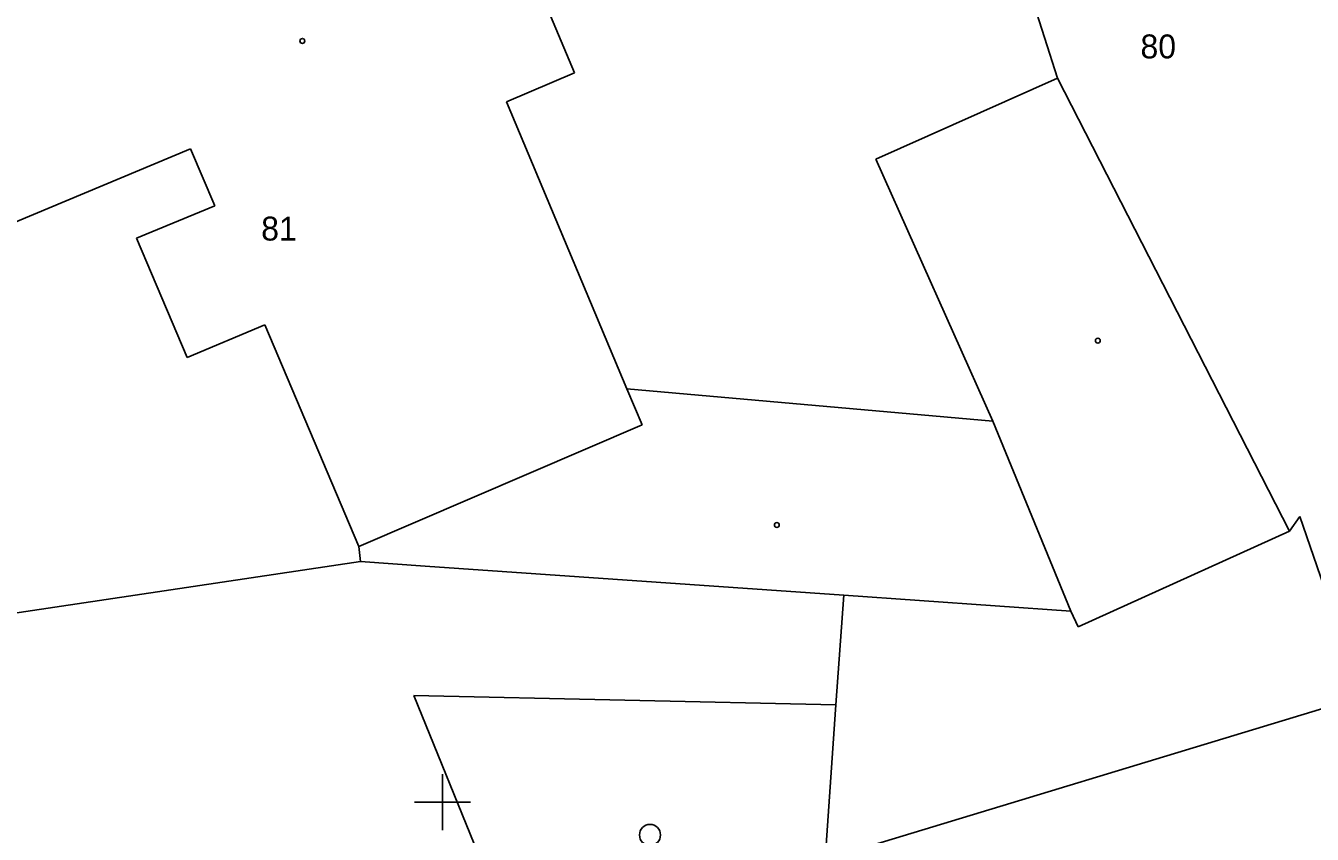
# Model space of a CAD drawing. Extents: x -711081 to -709338, y -1025122 to -1024092.
# Drawn here: x -709957.41 to -709934.53, y -1024625.57 to -1024611.19 of the extents above; entities that cross this region are included whole.
import ezdxf

# ---------------------------------------------------------------- set-up
doc = ezdxf.new("R2010")
doc.units = 0
for name, color, linetype in [('Z_hektometricka_sit', 7, 'Continuous'), ('Z_katastr_cisla_stavebni', 7, 'Continuous'), ('Z_katastr_hranice', 7, 'Continuous'), ('Z_katastr_vnitrni_kresba', 7, 'Continuous'), ('Z_katastr_znacky_budov', 7, 'Continuous'), ('Z_katastr_znacky_kultur', 7, 'Continuous')]:
    doc.layers.add(name, color=color, linetype=linetype)

msp = doc.modelspace()

# ---------------------------------------------------------------- linework, layer by layer
at = {"layer": 'Z_hektometricka_sit'}
for p, q in [((-709950, -1024624.5), (-709950, -1024625.5)), ((-709950.5, -1024625), (-709949.5, -1024625))]:
    msp.add_line(p, q, dxfattribs=at)
at = {"layer": 'Z_katastr_hranice'}
for p, q in [((-709942.18, -1024602.36), (-709939.06, -1024612.12)), ((-709939.06, -1024612.12), (-709934.93, -1024620.18)), ((-709934.93, -1024620.18), (-709934.75, -1024619.92)), ((-709934.75, -1024619.92), (-709934.32, -1024621.16)), ((-709958.51, -1024621.77), (-709951.46, -1024620.72)), ((-709951.46, -1024620.72), (-709950.31, -1024620.8)), ((-709950.31, -1024620.8), (-709942.86, -1024621.32)), ((-709942.86, -1024621.32), (-709943, -1024623.27)), ((-709948.08, -1024629.07), (-709950.51, -1024623.1)), ((-709950.51, -1024623.1), (-709943, -1024623.27)), ((-709943.19, -1024626.02), (-709933.61, -1024623.11)), ((-709943, -1024623.27), (-709943.19, -1024626.02))]:
    msp.add_line(p, q, dxfattribs=at)
at = {"layer": 'Z_katastr_vnitrni_kresba'}
for p, q in [((-709948.41, -1024610.22), (-709947.65, -1024612.03)), ((-709947.65, -1024612.03), (-709948.86, -1024612.54)), ((-709942.29, -1024613.56), (-709939.06, -1024612.12)), ((-709948.86, -1024612.54), (-709946.72, -1024617.65)), ((-709954.48, -1024613.38), (-709960.94, -1024616.08)), ((-709954.05, -1024614.39), (-709954.48, -1024613.38)), ((-709940.21, -1024618.22), (-709942.29, -1024613.56)), ((-709955.44, -1024614.97), (-709954.05, -1024614.39)), ((-709954.54, -1024617.09), (-709955.44, -1024614.97)), ((-709953.16, -1024616.51), (-709954.54, -1024617.09)), ((-709951.49, -1024620.45), (-709953.16, -1024616.51)), ((-709946.72, -1024617.65), (-709946.45, -1024618.29)), ((-709946.72, -1024617.65), (-709940.21, -1024618.22)), ((-709938.82, -1024621.6), (-709940.21, -1024618.22)), ((-709946.45, -1024618.29), (-709951.49, -1024620.45)), ((-709934.93, -1024620.18), (-709938.69, -1024621.88)), ((-709951.46, -1024620.72), (-709951.49, -1024620.45)), ((-709938.82, -1024621.6), (-709942.86, -1024621.32)), ((-709938.69, -1024621.88), (-709938.82, -1024621.6))]:
    msp.add_line(p, q, dxfattribs=at)
at = {"layer": 'Z_katastr_znacky_budov'}
for centre in [(-709952.492, -1024611.46), (-709938.342, -1024616.79), (-709944.052, -1024620.07)]:
    msp.add_circle(centre, 0.0437, dxfattribs=at)
at = {"layer": 'Z_katastr_znacky_kultur'}
msp.add_circle((-709946.308, -1024625.582), 0.187, dxfattribs=at)

# ---------------------------------------------------------------- texts
at = {"layer": 'Z_katastr_cisla_stavebni'}
for s, p in [('80', (-709937.583, -1024611.77)), ('81', (-709953.224, -1024615.01))]:
    msp.add_text(s, height=0.425, dxfattribs=at).set_placement(p)

doc.saveas('drawing.dxf')
